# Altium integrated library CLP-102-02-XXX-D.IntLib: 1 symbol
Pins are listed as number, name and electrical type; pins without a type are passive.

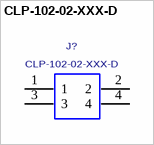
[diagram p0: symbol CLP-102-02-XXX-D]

## CLP-102-02-XXX-D
designator J?
LOW PROFILE 0.050"PITCH SMT DOUBLE ROW ASM, 4 PINS.; MANUFACTURER: SAMTEC
footprint CLP-102-02-XXX-D
pins: 1, 2, 3, 4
